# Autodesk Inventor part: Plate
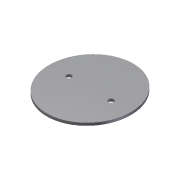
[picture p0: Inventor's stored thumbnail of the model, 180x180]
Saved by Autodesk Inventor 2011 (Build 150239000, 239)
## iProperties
Shininess: 77.0
Length Units: 11269
Angle Units: 11279
Time Units: 11290
Mass Units: 11283
Length Display Precision: 3
Angle Display Precision: 2
Created: 2002-01
Part Number: Plate
Document SubType Name: Modeling
Designer: ***
Density: 1 g/cm^3
Density: 0.0
Volumn: 0.0
Area: 0.0
PropertySet Name: Model Information
Control State: 0
Master: False
Checked Out: False
Author: ***
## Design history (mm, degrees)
sketch "Sketch1" dims "d0" = 102.5, "d1" = 96.9
  geometry: C1 r 6.25 at (-61.455, 0); C2 r 6.25 at (38.545, 0); 1 further point; 1 other entity
  constraints: 2 centre point, 2 other
  dimensions: "d2" = 12.5 diameter of C2; "d3" = 12.5 diameter of C1; "d4" = 100 distance of C2.centre C1.centre; "d5" = 50 distance of point (-11.455, 0) C2.centre
extrude "Extrusion1" new body sketch "Sketch1" stored distance "d6" = 6.3; taper "d7" = 0 deg
body "Solid1"
